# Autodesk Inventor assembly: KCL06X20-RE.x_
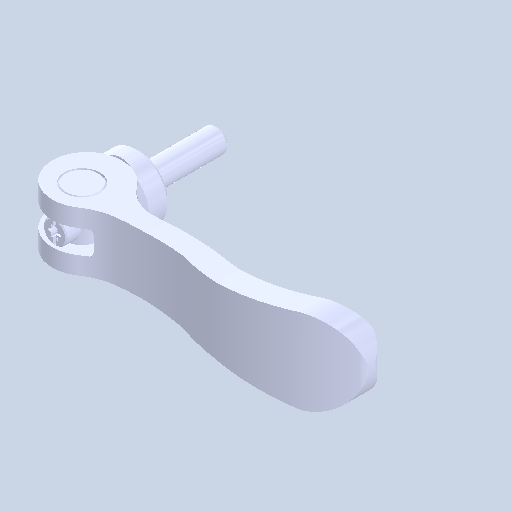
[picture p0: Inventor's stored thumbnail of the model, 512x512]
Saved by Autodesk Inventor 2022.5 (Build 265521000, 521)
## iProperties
Created: 2024-08
Part Number: KCL06X20-RE.x_
Document SubType Name: Assembly
Designer: ImaoCorp
Author: ImaoCorp
Sending System: SOLIDWORKS 2022-2022290
MC: AMD64
MC_MODEL: Intel64 Family 6 Model 60 Stepping 3, GenuineIntel
OS: Windows_NT
FRU: Parasolid Version 33.1, build 260,  4-25-2022
FORMAT: text
GUISE: transmit
KEY: FILEKCL06X20-RE.x_t
DATE: Thu Aug 29 10:49:39 2024
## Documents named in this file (5)
- Y:\5.更新分\2024年対応\1001_KCL\データ\kcl06x20-re\KCL06X20-RE.x_.iam
- Y:\5.更新分\2024年対応\1001_KCL\データ\kcl06x20-re\KCL06X20-RE_01.ipt
- Y:\5.更新分\2024年対応\1001_KCL\データ\kcl06x20-re\KCL06X20-RE_02.ipt
- Y:\5.更新分\2024年対応\1001_KCL\データ\kcl06x20-re\KCL06X20-RE_03.ipt
- Y:\5.更新分\2024年対応\1001_KCL\データ\kcl06x20-re\KCL06X20-RE_04.ipt
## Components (4 placed, 4 different names)
1. KCL06X20-RE_01
2. KCL06X20-RE_02
3. KCL06X20-RE_03
4. KCL06X20-RE_04
